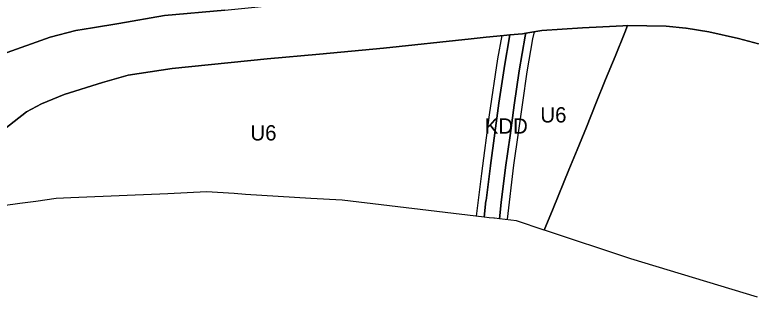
# Model space of a CAD drawing. Extents: x -284239 to -281592, y 34477 to 37267.
# Drawn here: x -282543.7 to -282059.7, y 34636 to 34820.9 of the extents above; entities that cross this region are included whole.
import ezdxf

# ---------------------------------------------------------------- set-up
doc = ezdxf.new("R2010")
doc.units = 0
for name, color, linetype in [('linie_rozgraniczajace', 7, 'Continuous'), ('linie_zabudowy_nieprzekraczalne', 7, 'Continuous'), ('oznaczenia_przeznaczen', 7, 'Continuous')]:
    doc.layers.add(name, color=color, linetype=linetype)

msp = doc.modelspace()

# ---------------------------------------------------------------- linework, layer by layer
at = {"layer": 'linie_rozgraniczajace'}
for points in [[(-282551.698, 34795.154), (-282520.433, 34806.265), (-282503.638, 34810.657), (-282492.832, 34812.392), (-282475.474, 34815.179), (-282445.759, 34820.347), (-282406.225, 34823.964), (-282360.49, 34828.615), (-282305.97, 34834.688), (-282271.337, 34837.805), (-282254.292, 34839.339), (-282223.802, 34842.698), (-282209.622, 34844.001), (-282198.128, 34845.058), (-282194.495, 34845.392), (-282166.182, 34847.995), (-282145.769, 34849.286), (-282122.255, 34849.028), (-282101.068, 34846.832), (-282079.627, 34843.782), (-282040.771, 34833.185)], [(-282406.225, 34823.964), (-282445.759, 34820.347), (-282475.474, 34815.179), (-282492.832, 34812.392), (-282503.638, 34810.657), (-282520.433, 34806.265), (-282551.698, 34795.154)], [(-282056.794, 34801.878), (-282070.024, 34805.451), (-282089.471, 34809.816), (-282104.155, 34812.263), (-282104.428, 34812.107), (-282117.346, 34813.5), (-282142.512, 34813.793), (-282145.769, 34813.758), (-282158.738, 34813.059), (-282172.125, 34812.337), (-282198.739, 34810.528), (-282209.181, 34808.823), (-282211.4, 34808.461), (-282219.585, 34807.765), (-282223.544, 34807.427), (-282235.145, 34806.191), (-282244.965, 34805.145), (-282302.353, 34799.03), (-282344.212, 34795.154), (-282378.578, 34792.053), (-282440.591, 34785.723), (-282469.531, 34781.33), (-282486.326, 34776.679), (-282511.39, 34768.669), (-282526.118, 34762.726), (-282535.937, 34757.3), (-282552.215, 34744.639)], [(-282057.54, 34636.03), (-282140.42, 34661.16), (-282197.02, 34679.87), (-282197.096, 34679.896), (-282191.171, 34694.157), (-282181.006, 34719.341), (-282175.587, 34732.552), (-282169.53, 34747.393), (-282163.402, 34762.801), (-282156.92, 34778.563), (-282150.722, 34793.688), (-282144.376, 34809.263), (-282142.512, 34813.793), (-282117.346, 34813.5), (-282104.428, 34812.107), (-282104.155, 34812.263), (-282089.471, 34809.816), (-282070.024, 34805.451), (-282056.794, 34801.878)], [(-282552.215, 34744.639), (-282535.937, 34757.3), (-282526.118, 34762.726), (-282511.39, 34768.669), (-282486.326, 34776.679), (-282469.531, 34781.33), (-282440.591, 34785.723), (-282378.578, 34792.053), (-282344.212, 34795.154), (-282302.353, 34799.03), (-282244.965, 34805.145), (-282235.145, 34806.191), (-282223.544, 34807.427), (-282219.585, 34807.765), (-282223.402, 34785.935), (-282223.409, 34785.853), (-282223.423, 34785.8), (-282226.757, 34763.099), (-282226.764, 34763.037), (-282229.357, 34743.314), (-282232.369, 34722.228), (-282232.373, 34722.169), (-282232.381, 34722.141), (-282235.238, 34699.281), (-282235.241, 34699.224), (-282235.248, 34699.196), (-282236.401, 34688.488), (-282236.415, 34688.353), (-282329.4, 34699.53), (-282349.97, 34700.7), (-282392.71, 34703.35), (-282400, 34703.85), (-282418.1, 34705.09), (-282443.57, 34703.77), (-282470.05, 34702.67), (-282507.03, 34701.06), (-282516.64, 34700.61), (-282529.89, 34698.66), (-282540.45, 34697.3), (-282551.35, 34695.9)]]:
    msp.add_lwpolyline(points, dxfattribs=at)
for points in [[(-282226.471, 34687.299), (-282225.31, 34698.083), (-282222.463, 34720.857), (-282219.453, 34741.927), (-282219.448, 34741.974), (-282216.858, 34761.684), (-282213.539, 34784.28), (-282209.593, 34806.852), (-282209.181, 34808.823), (-282198.739, 34810.528), (-282172.125, 34812.337), (-282158.738, 34813.059), (-282145.769, 34813.758), (-282142.512, 34813.793), (-282144.376, 34809.263), (-282150.722, 34793.688), (-282156.92, 34778.563), (-282163.402, 34762.801), (-282169.53, 34747.393), (-282175.587, 34732.552), (-282181.006, 34719.341), (-282191.171, 34694.157), (-282197.096, 34679.896), (-282215.23, 34686.04)], [(-282236.415, 34688.353), (-282236.401, 34688.488), (-282235.248, 34699.196), (-282235.241, 34699.224), (-282235.238, 34699.281), (-282232.381, 34722.141), (-282232.373, 34722.169), (-282232.369, 34722.228), (-282229.357, 34743.314), (-282226.764, 34763.037), (-282226.757, 34763.099), (-282223.423, 34785.8), (-282223.409, 34785.853), (-282223.402, 34785.935), (-282219.585, 34807.765), (-282211.4, 34808.461), (-282209.181, 34808.823), (-282209.593, 34806.852), (-282213.539, 34784.28), (-282216.858, 34761.684), (-282219.448, 34741.974), (-282219.453, 34741.927), (-282222.463, 34720.857), (-282225.31, 34698.083), (-282226.471, 34687.299), (-282229.78, 34687.67), (-282230.105, 34687.698), (-282233.23, 34687.97)]]:
    msp.add_lwpolyline(points, close=True, dxfattribs=at)
at = {"layer": 'linie_zabudowy_nieprzekraczalne'}
for points in [[(-282241.351, 34689.17), (-282238.043, 34717.018), (-282232.884, 34755.448), (-282227.592, 34792.159), (-282224.587, 34807.308)], [(-282203.808, 34809.703), (-282204.706, 34805.256), (-282208.542, 34783.56), (-282211.453, 34763.386), (-282214.098, 34743.674), (-282217.273, 34722.508), (-282221.375, 34687.053)]]:
    msp.add_lwpolyline(points, dxfattribs=at)

# ---------------------------------------------------------------- texts
at = {"layer": 'oznaczenia_przeznaczen'}
for s, p in [('U6', (-282199.663, 34750.422)), ('KDD', (-282236.095, 34743.108)), ('U6', (-282389.474, 34738.641))]:
    msp.add_text(s, height=10, dxfattribs=at).set_placement(p)

doc.saveas('drawing.dxf')
